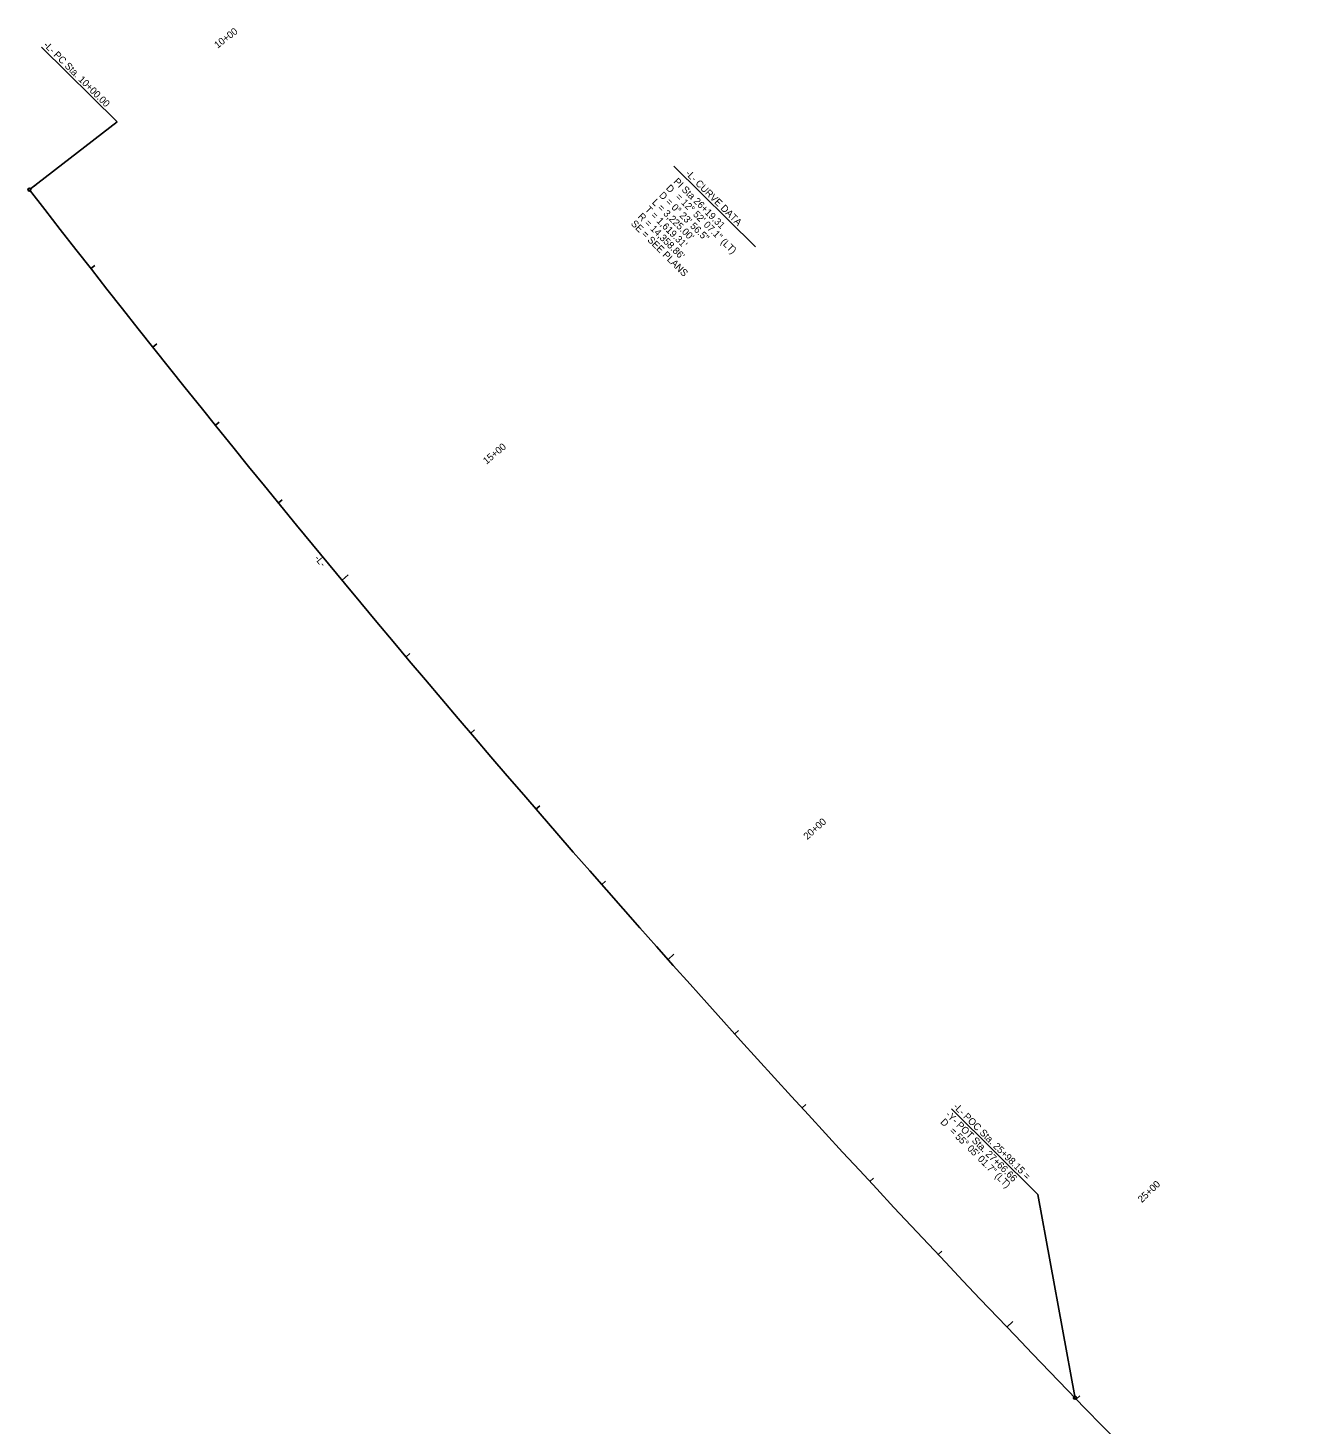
# Model space of a CAD drawing. Extents: x 1602281 to 1604813, y 908112 to 910586.
# Drawn here: x 1602281 to 1603569, y 909190 to 910586 of the extents above; entities that cross this region are included whole.
import ezdxf

# ---------------------------------------------------------------- set-up
doc = ezdxf.new("R2010")
doc.units = 0
for name, color, linetype in [('Exist Environmental Endangered Plant Boundary Cogo Point CELL', 7, 'Continuous'), ('Exist Environmental Wetland Boundary Cogo Comment', 7, 'Continuous'), ('Exist Environmental Wetland Boundary Cogo Elevation', 7, 'Continuous'), ('Exist Hydro Jurisdictional Stream or Body of Water NEU Mitigable Cogo Comment', 7, 'Continuous'), ('Exist Hydro Jurisdictional Stream or Body of Water NEU Mitigable Cogo Elevation', 7, 'Continuous'), ('Exist Hydro Jurisdictional Stream or Body of Water NEU Mitigable Cogo Point CELL', 7, 'Continuous'), ('Exist Hydro Jurisdictional Stream or Body of Water NEU NonMitigable', 7, 'Continuous')]:
    doc.layers.add(name, color=color, linetype=linetype)

msp = doc.modelspace()

# ---------------------------------------------------------------- linework, layer by layer
at = {"layer": 'Exist Environmental Endangered Plant Boundary Cogo Point CELL'}
msp.add_line((1602927.3, 910447.7), (1603008.8, 910367), dxfattribs=at)
at = {"layer": 'Exist Environmental Wetland Boundary Cogo Comment'}
for p, q in [((1602344.4, 910345.1), (1602348.3, 910348.2)), ((1602406.4, 910266.7), (1602410.3, 910269.8)), ((1602468.9, 910188.6), (1602472.8, 910191.7)), ((1602531.9, 910111), (1602535.8, 910114.1)), ((1602659.6, 909957), (1602663.4, 909960.3)), ((1602724.3, 909880.8), (1602728.1, 909884)), ((1602789.4, 909804.9), (1602793.2, 909808.2)), ((1602855.1, 909729.5), (1602858.9, 909732.8)), ((1602988.1, 909580.2), (1602991.8, 909583.5)), ((1603055.4, 909506.2), (1603059.1, 909509.5)), ((1603123.2, 909432.6), (1603126.8, 909436)), ((1603191.5, 909359.6), (1603195.1, 909363)), ((1603329.6, 909214.9), (1603333.2, 909218.4))]:
    msp.add_line(p, q, dxfattribs=at)
msp.add_circle((1602283, 910424.1), 1.5, dxfattribs=at)
at = {"layer": 'Exist Environmental Wetland Boundary Cogo Elevation'}
for p, q in [((1602283, 910424.1), (1602289.3, 910429)), ((1602595.5, 910033.8), (1602601.6, 910038.9)), ((1602921.4, 909654.6), (1602927.3, 909659.9)), ((1603260.3, 909287), (1603266, 909292.5))]:
    msp.add_line(p, q, dxfattribs=at)
at = {"layer": 'Exist Hydro Jurisdictional Stream or Body of Water NEU Mitigable Cogo Comment'}
for p, q in [((1602370.7, 910491.8), (1602295.2, 910566.6)), ((1602284.2, 910425), (1602370.7, 910491.8)), ((1603204.7, 909505.2), (1603291.2, 909419.7)), ((1603328, 909217.7), (1603291.2, 909419.7))]:
    msp.add_line(p, q, dxfattribs=at)
msp.add_circle((1603328.3, 909216.3), 1.5, dxfattribs=at)
at = {"layer": 'Exist Hydro Jurisdictional Stream or Body of Water NEU Mitigable Cogo Point CELL'}
msp.add_arc((1613646.3, 919202), 14358.9, 217.68536, 230.55399, dxfattribs=at)
at = {"layer": 'Exist Hydro Jurisdictional Stream or Body of Water NEU NonMitigable'}
msp.add_arc((1613646.3, 919202), 14358.9, 217.68536, 230.55399, dxfattribs=at)

# ---------------------------------------------------------------- texts
at = {"layer": 'Exist Environmental Endangered Plant Boundary Cogo Point CELL'}
for s, rotation, p in [('-L- CURVE DATA', 315.2975, (1602938.3, 910439.6)), ('D', 315.2976, (1602918.9, 910425)), ('PI Sta 26+19.31', 315.2976, (1602926.4, 910431.6)), ("L = 3,225.00'", 315.2976, (1602904.9, 910410.8)), ('D = 0%%d 23\' 56.5"', 315.2976, (1602911.9, 910417.9)), ('= 12%%d 52\' 07.1" (LT)', 315.2976, (1602928.3, 910416.2)), ("R = 14,358.86'", 315.2976, (1602890.8, 910396.6)), ("T = 1,619.31'", 315.2976, (1602897.8, 910403.7)), ('SE = SEE PLANS', 315.2976, (1602883.8, 910389.5))]:
    msp.add_text(s, height=7, rotation=rotation, dxfattribs=at).set_placement(p)
at = {"layer": 'Exist Hydro Jurisdictional Stream or Body of Water NEU Mitigable Cogo Comment'}
for s, rotation, p in [('-L- PC Sta. 10+00.00', 315.2977, (1602296.6, 910568)), ('-L- POC Sta. 25+98.15 =', 315.2976, (1603206.1, 909506.7)), ('D', 315.2976, (1603193.1, 909491.4)), ('-Y- POT Sta. 27+66.66', 315.2976, (1603198.4, 909498.8)), ('= 55%%d 05\' 01.7" (LT)', 315.2976, (1603202.3, 909482.3))]:
    msp.add_text(s, height=7, rotation=rotation, dxfattribs=at).set_placement(p)
at = {"layer": 'Exist Hydro Jurisdictional Stream or Body of Water NEU Mitigable Cogo Elevation'}
for s, rotation, p in [('10+00', 37.6854, (1602471.1, 910564.9)), ('15+00', 39.6805, (1602740, 910149.1)), ('20+00', 41.6756, (1603060.6, 909773.8)), ('25+00', 43.6708, (1603395.1, 909410.9))]:
    msp.add_text(s, height=7, rotation=rotation, dxfattribs=at).set_placement(p)
at = {"layer": 'Exist Hydro Jurisdictional Stream or Body of Water NEU NonMitigable'}
msp.add_text('-L-', height=7, rotation=309.6024, dxfattribs=at).set_placement((1602567.6, 910055.2))

doc.saveas('drawing.dxf')
